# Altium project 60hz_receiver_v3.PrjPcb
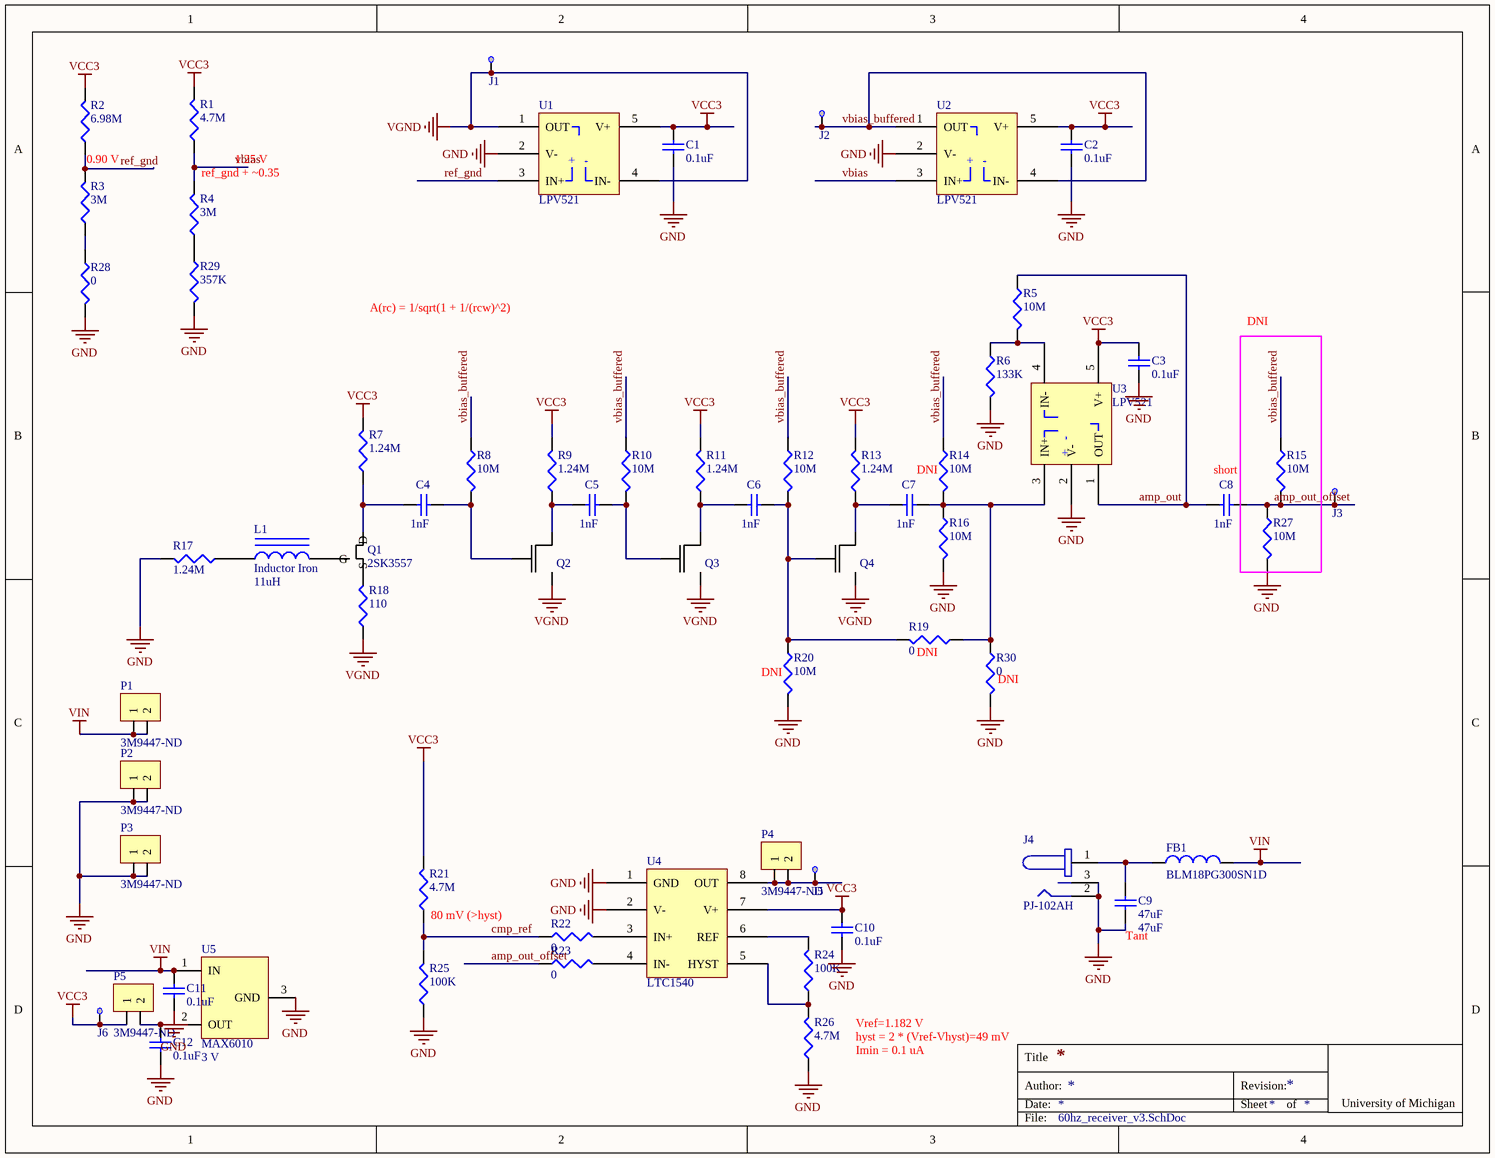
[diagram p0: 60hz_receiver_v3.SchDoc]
1 sheet, 64 parts. Net scope: global (net labels, ports and power ports of the same name join across sheets).
Board file: 60hz_receiver_v3.PcbDoc

## Sheet 60hz_receiver_v3.SchDoc
size Letter

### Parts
C1  value 0.1uF  [1608[0603]]  (hidden comment: Cap Semi)
C2  value 0.1uF  [1608[0603]]  (hidden comment: Cap Semi)
C3  value 0.1uF  [1608[0603]]  (hidden comment: Cap Semi)
C4  value 1nF  [1608[0603]]  (hidden comment: Cap Semi)
C5  value 1nF  [1608[0603]]  (hidden comment: Cap Semi)
C6  value 1nF  [1608[0603]]  (hidden comment: Cap Semi)
C7  value 1nF  [1608[0603]]  (hidden comment: Cap Semi)
C8  value 1nF  [1608[0603]]  (hidden comment: Cap Semi)
C9  47uF  [C1210]
C10  value 0.1uF  [1608[0603]]  (hidden comment: Cap Semi)
C11  value 0.1uF  [1608[0603]]  (hidden comment: Cap Semi)
C12  value 0.1uF  [1608[0603]]  (hidden comment: Cap Semi)
FB1  BLM18PG300SN1D  [1608[0603]]
J1  5004  [TestPoint]  (value not drawn)
J2  5004  [TestPoint]  (value not drawn)
J3  5004  [TestPoint]  (value not drawn)
J4  PJ-102AH  [PJ-102AH]
J5  5004  [TestPoint]  (value not drawn)
J6  5004  [TestPoint]  (value not drawn)
L1  Inductor Iron  value 11uH  [charging coil]
P1  Supplier Part Number 1: 3M9447-ND  [1x2 header]  (hidden comment: 1 x 2 header)
P2  Supplier Part Number 1: 3M9447-ND  [1x2 header]  (hidden comment: 1 x 2 header)
P3  Supplier Part Number 1: 3M9447-ND  [1x2 header]  (hidden comment: 1 x 2 header)
P4  Supplier Part Number 1: 3M9447-ND  [1x2 header]  (hidden comment: 1 x 2 header)
P5  Supplier Part Number 1: 3M9447-ND  [1x2 header]  (hidden comment: 1 x 2 header)
Q1  2SK3557  [SOT23-3N]
Q2  Si2312CDS  [SOT23-3N]  (value not drawn)
Q3  Si2312CDS  [SOT23-3N]  (value not drawn)
Q4  Si2312CDS  [SOT23-3N]  (value not drawn)
R1  value 4.7M  [J1-0603]  (hidden comment: Res3)
R2  value 6.98M  [J1-0603]  (hidden comment: Res3)
R3  value 3M  [J1-0603]  (hidden comment: Res3)
R4  value 3M  [J1-0603]  (hidden comment: Res3)
R5  value 10M  [J1-0603]  (hidden comment: Res3)
R6  value 133K  [J1-0603]  (hidden comment: Res3)
R7  value 1.24M  [J1-0603]  (hidden comment: Res3)
R8  value 10M  [J1-0603]  (hidden comment: Res3)
R9  value 1.24M  [J1-0603]  (hidden comment: Res3)
R10  value 10M  [J1-0603]  (hidden comment: Res3)
R11  value 1.24M  [J1-0603]  (hidden comment: Res3)
R12  value 10M  [J1-0603]  (hidden comment: Res3)
R13  value 1.24M  [J1-0603]  (hidden comment: Res3)
R14  value 10M  [J1-0603]  (hidden comment: Res3)
R15  value 10M  [J1-0603]  (hidden comment: Res3)
R16  value 10M  [J1-0603]  (hidden comment: Res3)
R17  value 1.24M  [J1-0603]  (hidden comment: Res3)
R18  value 110  [J1-0603]  (hidden comment: Res3)
R19  value 0  [J1-0603]  (hidden comment: Res3)
R20  value 10M  [J1-0603]  (hidden comment: Res3)
R21  value 4.7M  [J1-0603]  (hidden comment: Res3)
R22  value 0  [J1-0603]  (hidden comment: Res3)
R23  value 0  [J1-0603]  (hidden comment: Res3)
R24  value 100K  [J1-0603]  (hidden comment: Res3)
R25  value 100K  [J1-0603]  (hidden comment: Res3)
R26  value 4.7M  [J1-0603]  (hidden comment: Res3)
R27  value 10M  [J1-0603]  (hidden comment: Res3)
R28  value 0  [J1-0603]  (hidden comment: Res3)
R29  value 357K  [J1-0603]  (hidden comment: Res3)
R30  value 0  [J1-0603]  (hidden comment: Res3)
U1  LPV521  [SC70-5]
U2  LPV521  [SC70-5]
U3  LPV521  [SC70-5]
U4  LTC1540  [SOIC-8]
U5  MAX6010  value 3 V  [SOT23-3N]

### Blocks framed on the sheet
DNI: R15 R27

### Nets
GND: C1.1 C2.1 C3.1 C9.1 C10.1 C11.1 C12.1 J4.2 J4.3 P2.1 P2.2 P3.1 P3.2 R6.2 R16.2 R17.2 R20.2 R25.1 R26.1 R27.2 R28.2 R29.2 R30.2 U1.2(V-) U2.2(V-) U3.2(V-) U4.1(GND) U4.2(V-) U5.3(GND)
VCC3: C1.2 C2.2 C3.2 C10.2 J6.1(TB) P5.1 R1.1 R2.2 R7.2 R9.2 R11.2 R13.2 R21.2 U1.5(V+) U2.5(V+) U3.5(V+) U4.7(V+)
VGND: J1.1(TB) Q2.2(S) Q3.2(S) Q4.2(S) R18.1 U1.1(OUT) U1.4(IN-)
VIN: C11.2 FB1.2 P1.1 P1.2 U5.1(IN)
amp_out: C8.1 R5.1 U3.1(OUT)
amp_out_offset: C8.2 J3.1(TB) R15.2 R23.1 R27.1
cmp_ref: R21.1 R22.1 R25.2
ref_gnd: R2.1 R3.2 U1.3(IN+)
vbias: R1.2 R4.1 U2.3(IN+)
vbias_buffered: J2.1(TB) R8.1 R10.1 R12.1 R14.1 R15.1 U2.1(OUT) U2.4(IN-)
NetC4_1: C4.1 Q1.2(D) R7.1
NetC4_2: C4.2 Q2.1(G) R8.2
NetC5_1: C5.1 Q2.3(D) R9.1
NetC5_2: C5.2 Q3.1(G) R10.2
NetC6_1: C6.1 Q3.3(D) R11.1
NetC6_2: C6.2 Q4.1(G) R12.2 R19.2 R20.1
NetC7_1: C7.1 Q4.3(D) R13.1
NetC7_2: C7.2 R14.2 R16.1 R19.1 R30.1 U3.3(IN+)
NetC9_2: C9.2 FB1.1 J4.1
NetC12_2: C12.2 P5.2 U5.2(OUT)
NetJ5_1: J5.1(TB) P4.1 P4.2 U4.8(OUT)
NetL1_1: L1.1 R17.1
NetL1_2: L1.2 Q1.3(G)
NetQ1_1: Q1.1(S) R18.2
NetR3_1: R3.1 R28.1
NetR4_2: R4.2 R29.1
NetR5_2: R5.2 R6.1 U3.4(IN-)
NetR22_2: R22.2 U4.3(IN+)
NetR23_2: R23.2 U4.4(IN-)
NetR24_1: R24.1 R26.2 U4.5(HYST)
NetR24_2: R24.2 U4.6(REF)

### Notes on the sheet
- 0.90 V
- (near R1) 1.25 V
- (near R4) ref_gnd + ~0.35
- A(rc) = 1/sqrt(1 + 1/(rcw)^2)
- (near R14) DNI
- short
- (near R20) DNI
- (near R19) DNI
- (near R30) DNI
- (near C9) Tant
- Labels drawn without touching a wire or pin: 80 mV (>hyst), hyst = 2 * (Vref-Vhyst)=49 mV, Imin = 0.1 uA, Vref=1.182 V

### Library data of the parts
C1-C12 = Cap Semi: Capacitor (Semiconductor SIM Model)
FB1 = Ferrite Bead: FERRITE CHIP 30 OHM 1000MA 0603
J1-J3 J5 J6 = TestPoint: TEST POINT PC MINI .040"D YELLOW
J4 = PJ-102AH: CONN PWR JACK 2.1X5.5MM HIGH CUR
L1 = Inductor Iron: Magnetic-Core Inductor
P1-P5 = 1 x 2 header: 100 mils standard header
Q1 = 2SK3557: N-Channel JFET
Q2-Q4 = Si2312CDS: N-Channel 20 V (D-S) MOSFET
R1-R30 = Res3: Resistor
U1-U3 = LPV521: Nanopower, 1.8V, RRIO, CMOS Input, Operational Amplifier
U4 = LTC1540: Nanopower Comparator  with Reference
U5 = MAX6010: Precision Micropower Shunt Voltage Reference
